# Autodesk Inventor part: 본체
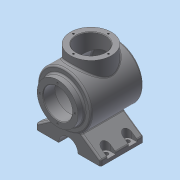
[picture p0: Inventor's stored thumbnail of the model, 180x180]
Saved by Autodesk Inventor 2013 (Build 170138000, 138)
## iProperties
Created: 2017-04
Part Number: 본체
Material: 일반
Document SubType Name: Modeling
Designer: Administrator
Density: 1 g/cm^3
Author: Administrator
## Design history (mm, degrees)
sketch "스케치1"
  geometry: L1 (-60, 0)-(60, 0); L2 (-60, 27)-(-60, 38); L3 (-60, 38)-(-48, 38); L4 (-48, 38)-(-48, 50); L5 (-48, 50)-(48.336, 50); L6 (-60, 27)-(-38, 27); L7 (-38, 27)-(-38, 40); L8 (-38, 40)-(41.916, 40); A1 r 113 centre (-53, 0) between (60, 0) and (48.336, 50); A2 r 103 centre (-53, 0) between (50, 0) and (41.916, 40); 2 further points
  constraints: 16 end point, 4 parallel, 4 point on circle, 3 perpendicular, 2 centre point, 2 point on line, 1 coincident, 1 horizontal, 1 horizontal alignment, 1 midpoint
  dimensions: "d1" = 120 distance of L1.start L1.end; "d3" = 226 diameter of A1; "d4" = 10 radial gap between concentric circles of A1 A2; "d5" = 54 diameter of L6 L1; "d6" = 76 diameter of L3 L1; "d7" = 80 diameter of L8 L1; "d9" = 100 diameter of L5 L1; "d10" = 12 distance of L2.end L3.end; "d11" = 22 distance of L2.start L6.end
revolve "회전1" sketch "스케치1" stored, may be unused: angle "d12" = 90 deg
node "작업 평면1"
sketch "스케치2"
  geometry: L1 (-21.584, -45.101)-(-60, -72); L2 (-60, -72)-(-60, -82); L3 (-60, -82)-(60, -82); L4 (60, -82)-(60, -72); L5 (60, -72)-(21.584, -45.101); A1 r 50 centre (0, 0) between (-21.584, -45.101) and (21.584, -45.101) reference; 2 further points
  constraints: 10 end point, 2 perpendicular, 2 point on circle, 1 midpoint, 1 parallel, 1 vertical, 1 vertical alignment
  dimensions: "d23" = 82 distance from line of point (0, 0) L3; "d24" = 10 distance of L1.end L2.end; "d25" = 55 deg angle of L2 L1; "d26" = 55 deg angle of L4 L5; "d27" = 120 distance of L2.end L3.end
extrude "돌출1" join sketch "스케치2" distance "d28" = 80; taper "d29" = 0 deg
sketch "스케치3"
  geometry: L1 (-60, -82)-(60, -82) reference; C1 r 18 at (0, -82)
  constraints: 1 centre point, 1 midpoint
  dimensions: "d30" = 36 diameter of C1
extrude "돌출2" cut sketch "스케치3" stored distance "d32" = 80; taper "d33" = 0 deg
node "작업 평면2"
sketch "스케치4"
  geometry: L1 (0, 0)-(-80, 0) reference; L2 (-68, 0)-(-68, -10); L3 (-52, -10)-(-52, 0); L4 (-28, 0)-(-28, -10); L5 (-12, -10)-(-12, 0); L6 (-80, 0)-(-80, -42) reference; A1 r 8 centre (-60, -10) between (-68, -10) and (-52, -10); A2 r 8 centre (-20, -10) between (-28, -10) and (-12, -10); 1 further point
  constraints: 8 end point, 4 point on circle, 4 point on line, 4 tangent, 3 perpendicular, 2 centre point, 1 parallel
  dimensions: "d35" = 20 distance from line of L6 A1.centre; "d36" = 10 distance from line of L1 A1.centre; "d37" = 40 distance of A2.centre A1.centre; "d38" = 10 distance from line of L1 A2.centre; "d39" = 8 radius of A1; "d40" = 8 radius of A2
extrude "돌출3" cut sketch "스케치4" stored distance "d41" = 80; taper "d42" = 0 deg
sketch "스케치5"
  geometry: L1 (0, 43.029)-(80, 43.029) reference; L2 (80, 43.029)-(80, 0) reference; L3 (80, 0)-(68, 0) reference; L4 (68, 0)-(68, 10) reference; L5 (52, 10)-(52, 0) reference; L6 (52, 0)-(28, 0) reference; L7 (28, 0)-(12, 0) reference; L8 (12, 0)-(0, 0) reference; L9 (0, 0)-(0, 43.029) reference; L10 (68, 0)-(52, 0) reference; L11 (28, 0)-(28, 10) reference; L12 (12, 10)-(12, 0) reference; L13 (80, 76.971)-(0, 76.971) reference; L14 (0, 76.971)-(0, 120) reference; L15 (0, 120)-(80, 120) reference; L16 (80, 120)-(80, 76.971) reference; C1 r 4 at (20, 10); C2 r 4 at (60, 10); A1 r 8 centre (20, 10) between (28, 10) and (12, 10) reference; A2 r 8 centre (60, 10) between (68, 10) and (52, 10) reference; A3 r 8 centre (20, 10) between (28, 10) and (12, 10) reference; 1 further point
  constraints: 2 centre point, 2 coincident, 1 equal radius
  dimensions: "d43" = 8 diameter of C1
extrude "돌출4" cut sketch "스케치5" stored distance "d45" = 80; taper "d46" = 0 deg
node "작업 평면3"
sketch "스케치6"
  geometry: L1 (8, -10)-(8, -110) reference; C1 r 38 at (-42, -60); 1 further point
  constraints: 1 centre point, 1 horizontal alignment
  dimensions: "d48" = 50 distance from line of L1 C1.centre; "d49" = 76 diameter of C1
extrude "돌출5" join sketch "스케치6" stored distance "d50" = 80; taper "d51" = 0 deg
sketch "스케치7"
  geometry: C1 r 38 at (0, 0) reference; C2 r 27 at (0, 0); 1 further point
  constraints: 1 centre point, 1 coincident
  dimensions: "d52" = 54 diameter of C2
extrude "돌출6" cut sketch "스케치7" stored distance "d54" = 80; taper "d55" = 0 deg
sketch "스케치8" dims "d56" = 65
  geometry: C1 r 38 at (0, 0) reference; C2 r 27 at (0, 0) reference; 2 further points
  constraints: 2 vertical alignment, 1 coincident, 2 other
hole "구멍1" sketch "스케치8" at (0, 32.5) diameter "d58" = 3.242; stored, may be unused: countersink angle "d62" = 90 deg, drill point angle "d64" = 118 deg; dims "d59" = 8, "d60" = 4, "d61" = 2, "d63" = 10
sketch "스케치9" dims "d68" = 65
  geometry: C1 r 27 at (0, 0) reference; C2 r 38 at (0, 0) reference; 3 further points
  constraints: 2 horizontal alignment, 1 coincident, 2 other
hole "구멍2" sketch "스케치9" at (-32.5, 0) diameter "d70" = 3.242; stored, may be unused: countersink angle "d74" = 90 deg, drill point angle "d76" = 118 deg; dims "d71" = 8, "d72" = 4, "d73" = 2, "d75" = 10
node "작업 평면4"
sketch "스케치10"
  geometry: 2 further points
  constraints: 1 coincident, 1 other
feature "엠보싱1" sketch "스케치10" dims "d1" = 120, "d3" = 226, "d4" = 10, "d5" = 54, "d6" = 76, "d7" = 80, "d9" = 100, "d10" = 12, "d11" = 22, "d23" = 82, "d24" = 10, "d25" = 55 deg, "d26" = 55 deg, "d27" = 120, "d81" = 0.5, "d82" = 0
fillet "모깎기1" dims "d83" = 3
chamfer "모따기1" distance "d84" = 1; stored, may be unused: second distance "d85" = 2, angle "d86" = 45 deg
fillet "모깎기2" dims "d87" = 3
fillet "모깎기3" dims "d88" = 3
node "솔리드1"
mirror "대칭1"
pattern_circular "원형 패턴1" dims angle "d66" = 360 deg
pattern_circular "원형 패턴2" dims angle "d78" = 360 deg
node "절단 모서리 투영1"
other parameters: "d13" = -8, "d34" = -6, "d47" = -147, "d80" = 89.75
